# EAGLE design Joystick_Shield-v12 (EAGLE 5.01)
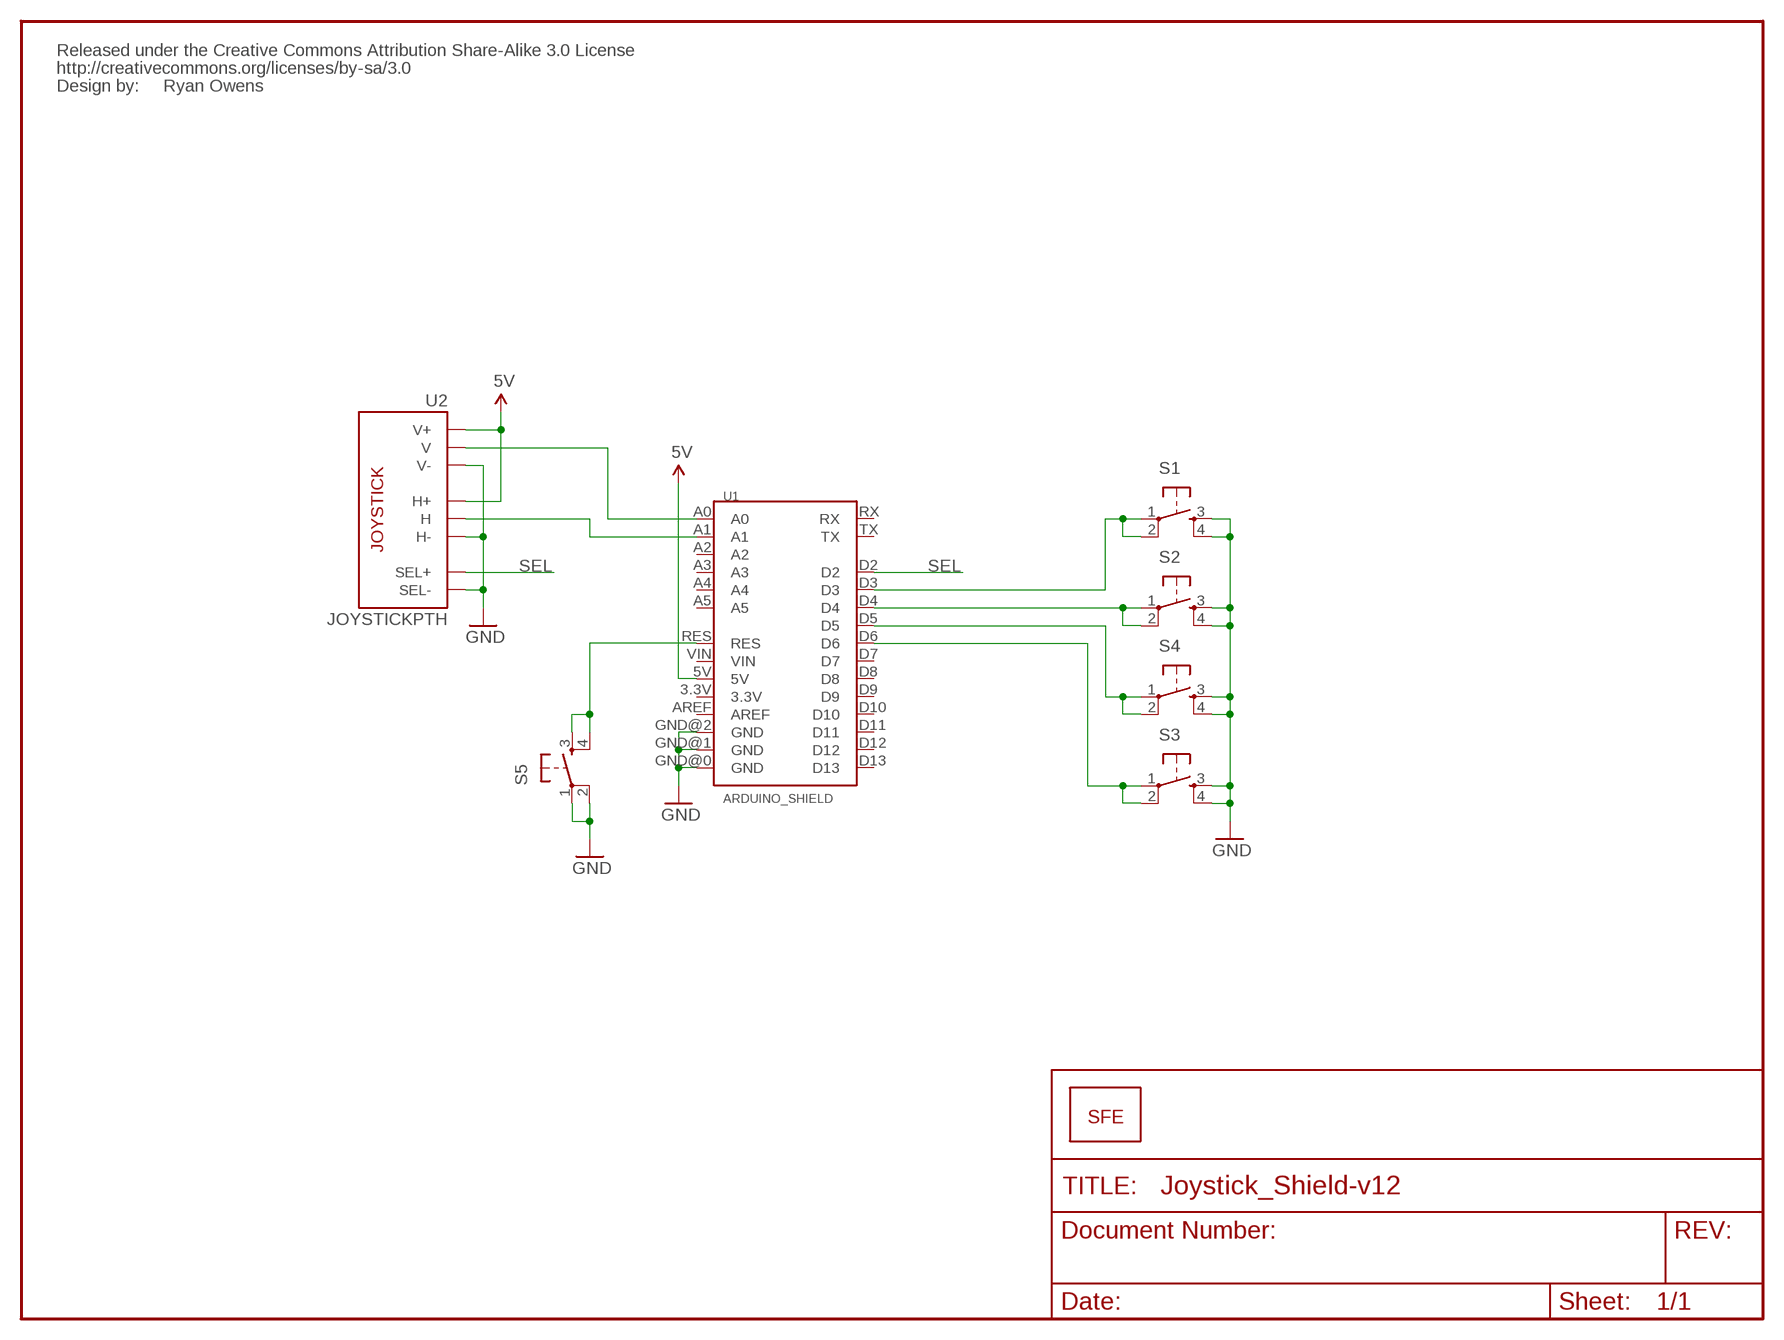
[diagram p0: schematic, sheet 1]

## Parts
JP1  LOGO-SFENEW  [SFE-NEW-WEBLOGO]
S1  TAC_SWITCH12MM  [TACTILE-PTH-12MM]
S2  TAC_SWITCH12MM  [TACTILE-PTH-12MM]
S3  TAC_SWITCH12MM  [TACTILE-PTH-12MM]
S4  TAC_SWITCH12MM  [TACTILE-PTH-12MM]
S5  TAC_SWITCHPTH  [TACTILE-PTH]
U1  ARDUINO_SHIELD  [DUEMILANOVE_SHIELD]
U2  JOYSTICKPTH  [JOYSTICK]
U$3  CREATIVE_COMMONS  [CREATIVE_COMMONS]

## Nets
5V: U1.5V U2.H1(H+) U2.V1(V+)
GND: S1.3 S1.4 S2.3 S2.4 S3.3 S3.4 S4.3 S4.4 S5.1 S5.2 U1.GND@0(GND) U1.GND@1(GND) U1.GND@2(GND) U2.B2A(SEL-) U2.H3(H-) U2.V3(V-)
N$1: S5.3 S5.4 U1.RES
N$3: U1.A0 U2.V2(V)
N$4: U1.A1 U2.H2(H)
N$6: S1.1 S1.2 U1.D3
N$7: S2.1 S2.2 U1.D4
N$8: S4.1 S4.2 U1.D5
N$9: S3.1 S3.2 U1.D6
SEL: U1.D2 U2.B1A(SEL+)
Unconnected: U1.3.3V U1.A2 U1.A3 U1.A4 U1.A5 U1.AREF U1.D7 U1.D8 U1.D9 U1.D10 U1.D11 U1.D12 U1.D13 U1.RX U1.TX U1.VIN

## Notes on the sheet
- Ryan Owens

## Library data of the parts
JP1 = SparkFun:LOGO-SFE: Spark Fun Electronics PCB Logo
S1-S5 = SparkFun:TAC_SWITCH: Momentary Switch Button commonly used for reset or general input. Spark Fun Electronics SKU : COM-00097
U1 = SparkFun:ARDUINO_SHIELD
U2 = SparkFun:JOYSTICK: Thumb Joystick Joystick commonly found in PS2 controllers. Two pots and a select switch. Footprint proven. Spark Fun Electronics SKU : COM-09032
U$3 = SparkFun:CREATIVE_COMMONS

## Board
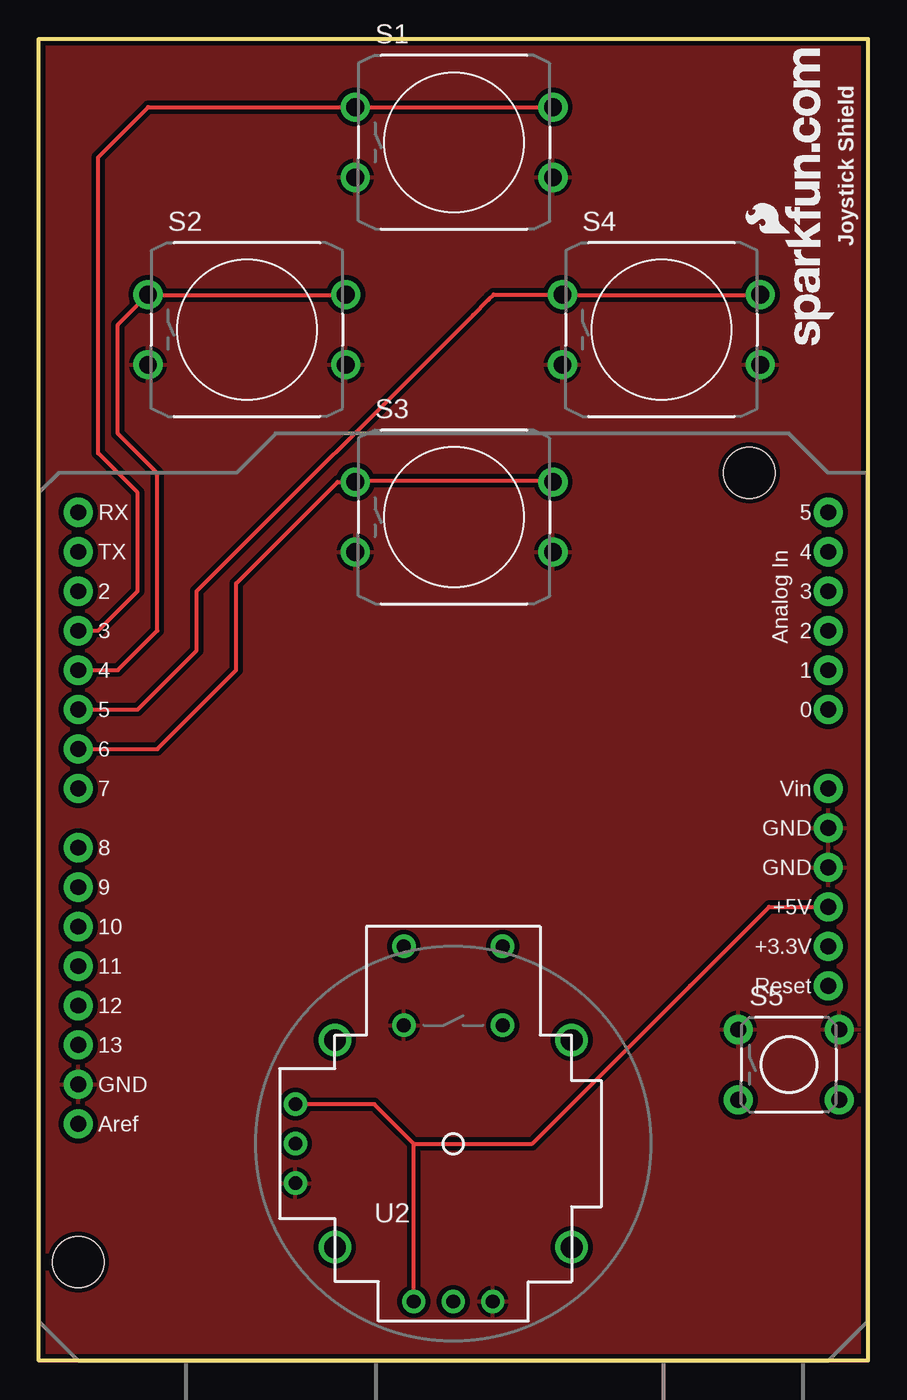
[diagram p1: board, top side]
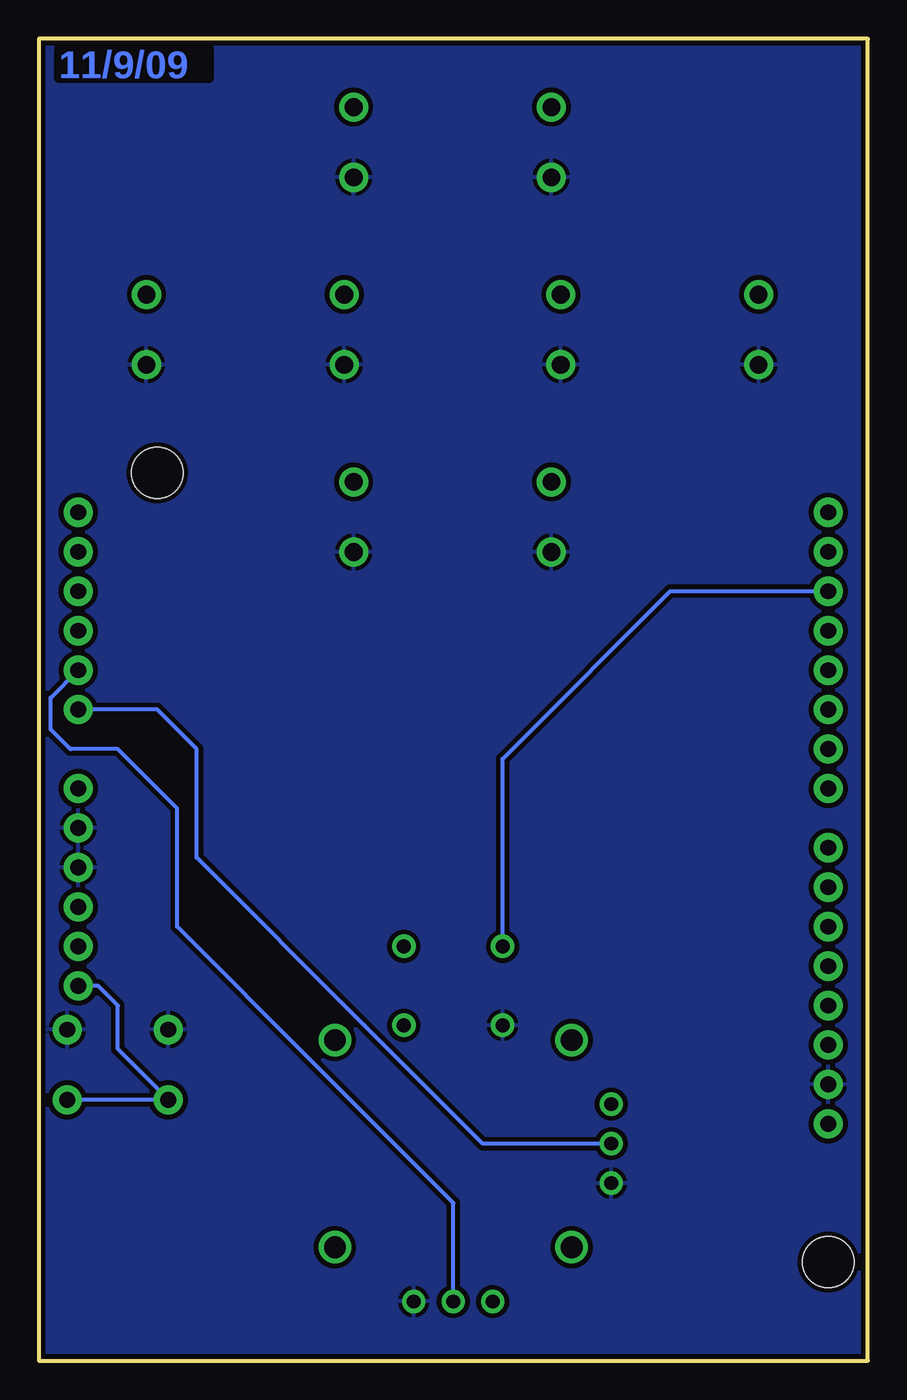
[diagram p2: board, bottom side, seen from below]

Size 53.34 x 85.09 mm. Coordinates in mm from the lower left corner, seen from the top.
Outline: 0,0 0,85.09 53.34,85.09 53.34,0 0,0
Copper layers (1*16): Top 0.035mm / dielectric 1.5mm / Bottom 0.035mm
Design rules "SparkFun": minimum track width 8mil, minimum drill 20mil, track to track 8mil, track to pad 8mil, pad to pad 8mil, via to via 8mil, smd to smd 8mil, copper to edge 9mil, drill to drill 8mil, minimum pad ring 12mil, minimum via ring 10mil, stop-mask expansion 4mil, vias tented up to drill 20mil, thermal gap 10mil

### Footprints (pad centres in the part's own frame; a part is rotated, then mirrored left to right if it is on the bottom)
TACTILE-PTH-12MM = drill 1.143 pad 1.88 round: 1 -0.597,4.496; 2 12.129,4.496; 3 -0.597,-0.025; 4 12.129,-0.025
TACTILE-PTH = drill 1.016 pad 1.88 round: 1 -3.251,2.261; 2 3.251,2.261; 3 -3.251,-2.261; 4 3.251,-2.261
DUEMILANOVE_SHIELD = drill 1.016 pad 1.88 round: 3.3V 50.8,26.67; 5V 50.8,29.21; A0 50.8,41.91; A1 50.8,44.45; A2 50.8,46.99; A3 50.8,49.53; A4 50.8,52.07; A5 50.8,54.61; AREF 2.54,15.24; D2 2.54,49.53; D3 2.54,46.99; D4 2.54,44.45; D5 2.54,41.91; D6 2.54,39.37; D7 2.54,36.83; D8 2.54,33.02; D9 2.54,30.48; D10 2.54,27.94; D11 2.54,25.4; D12 2.54,22.86; D13 2.54,20.32; GND@0 50.8,31.75; GND@1 50.8,34.29; GND@2 2.54,17.78; RES 50.8,24.13; RX 2.54,54.61; TX 2.54,52.07; VIN 50.8,36.83 | hole 3.302: 45.72,57.15; 2.54,6.35
JOYSTICK = drill 0.9 round: B1A -3.175,12.7; B1B 3.175,12.7; B2A -3.175,7.62; B2B 3.175,7.62 | drill 0.889 round: H1 -2.54,-10.16; H2 0,-10.16; H3 2.54,-10.16; V1 -10.16,2.54; V2 -10.16,0; V3 -10.16,-2.54 | drill 1.397 round: MOUNT1 -7.62,6.668; MOUNT2 -7.62,-6.668; MOUNT3 7.62,-6.668; MOUNT4 7.62,6.668

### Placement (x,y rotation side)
JP1  51.18,65.41 90 top
S1  20.95,76.2 0 top
S2  7.62,64.14 0 top
S3  20.95,52.07 0 top
S4  34.29,64.14 0 top
S5  48.26,19.05 0 top
U1  0,0 0 top
U2  26.67,13.97 0 top
U$3  not placed on the board

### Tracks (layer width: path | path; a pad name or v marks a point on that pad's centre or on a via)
5V
  Top 0.254: U2.V1 21.59,16.51 24.13,13.97 | U2.H1 24.13,13.97 | U1.5V 46.99,29.21 41.91,24.13 31.75,13.97 24.13,13.97
GND
  pour Top (isolate 0.305): 0,0 53.34,0 53.34,85.09 0,85.09
  pour Bottom (isolate 0.305): 0,0 53.34,0 53.34,85.09 0,85.09
N$1
  Bottom 0.254: 44.98,16.79 44.96,16.76 | S5.3 44.98,16.79 | S5.3 44.98,16.79 | S5.3 S5.4 | 44.98,16.79 44.96,16.76 | U1.RES 49.53,24.13 48.26,22.86 48.26,20.07 44.96,16.76 | 44.98,16.79 44.96,16.76 | S5.3 44.98,16.79
N$3
  Bottom 0.254: U2.V2 24.77,13.97 32.38,21.59 43.18,32.38 43.18,39.37 45.72,41.91 U1.A0
N$4
  Bottom 0.254: U2.H2 26.67,10.16 35.56,19.05 44.45,27.94 44.45,33.02 44.45,35.56 48.26,39.37 51.31,39.37 52.58,40.64 52.58,42.67 U1.A1
N$6
  Top 0.254: U1.D3 3.81,46.99 6.35,49.53 6.35,55.88 3.81,58.42 3.81,77.47 6.35,80.01 7.04,80.7 S1.1 20.36,80.68 20.32,80.64 S1.1 S1.2
N$7
  Top 0.254: U1.D4 5.08,44.45 7.62,46.99 7.62,57.15 5.08,59.69 5.08,66.69 S2.1 7.07,68.58 12.7,68.58 19.7,68.58 S2.2
N$8
  Top 0.254: U1.D5 6.35,41.91 10.16,45.72 10.16,49.53 27.94,67.31 28.93,68.3 28.96,68.33 29.26,68.63 S4.1 33.74,68.58 40.64,68.58 46.37,68.58 S4.2
N$9
  Top 0.254: U1.D6 7.62,39.37 12.7,44.45 12.7,49.53 12.7,50.04 19.23,56.57 S3.1 20.43,56.64 24.13,56.64 33.01,56.64 S3.2
SEL
  Bottom 0.254: U1.D2 12.7,49.53 22.86,39.37 23.5,38.73 U2.B1A

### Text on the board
Bottom: 11/9/09
tPlace: Joystick Shield
tValues: Ryan Owens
